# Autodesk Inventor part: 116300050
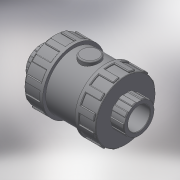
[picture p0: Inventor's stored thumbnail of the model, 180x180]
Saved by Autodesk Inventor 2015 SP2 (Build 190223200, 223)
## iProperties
Created: 2017-11
Part Number: 116300050
Material: Generic
Description: PLASSON AIR RELEASE VALVE CEM PVC 50
Document SubType Name: Modeling
Designer: KIM
Density: 1 g/cm^3
Appearance: Default
Author: KIM
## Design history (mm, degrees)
derived "116300 - 116900.ipt"
feature "Solid1::116300 - 116900.ipt"
tag "TaggingFeature1"
body "Solid1"
other parameters: "d0" = 142, "d2" = 96, "d3" = 31, "d5" = 21.7, "d8" = 86.4, "d13" = 1.5, "d23" = 31, "d24" = 92.16, "d25" = 1, "d26" = 1.5, "d27" = 14.4, "d28" = 7.2, "d29" = 23.25, "d30" = 0, "d35" = 1.5, "d39" = 48, "d45" = 360 deg, "d47" = 1, "d50" = 48, "d51" = 28.8, "d53" = 0, "d54" = 1.92, "d56" = 5, "d58" = 0, "d59" = 1.5, "d61" = 360 deg, "l_" = 31, "H_" = 142, "K_" = 96
